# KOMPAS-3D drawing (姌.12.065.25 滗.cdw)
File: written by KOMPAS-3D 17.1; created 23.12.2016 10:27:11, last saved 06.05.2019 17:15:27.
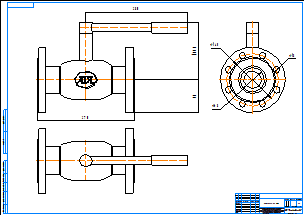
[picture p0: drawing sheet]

Sheet 1: A1, landscape

Title block, sheet 1: name: КШ.12.065.25 фф; material: Внимание! Данный продукт является объектом авторского права ООО «Торговый Дом АДЛ». / Запрещается изменение, копирование, распространение / (в том числе путем копирования на другие сайты и ресурсы в Интернете) / или любое иное использование информации и объектов без предварительного / согласия правообладателя (ООО «Торговый Дом АДЛ»).; sheets: 1; organisation: ООО "Торговый дом АДЛ"; sheet format: A1; stored path: C:\Users\tra\Desktop\2д чертежи\Шаровые краны БИВАЛ\КШ_Бивал_серия_11_12\KOMPAS_2D\КШ.12.065.25 фф.cdw

Views: Вид 1, Проекционный вид 2, Проекционный вид 3
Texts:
  Klimkovich
  ADL
Dimensions and other numbers on the sheet: 270; 159,3; 90; 280; 145; 68; 18; 1:1; 1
